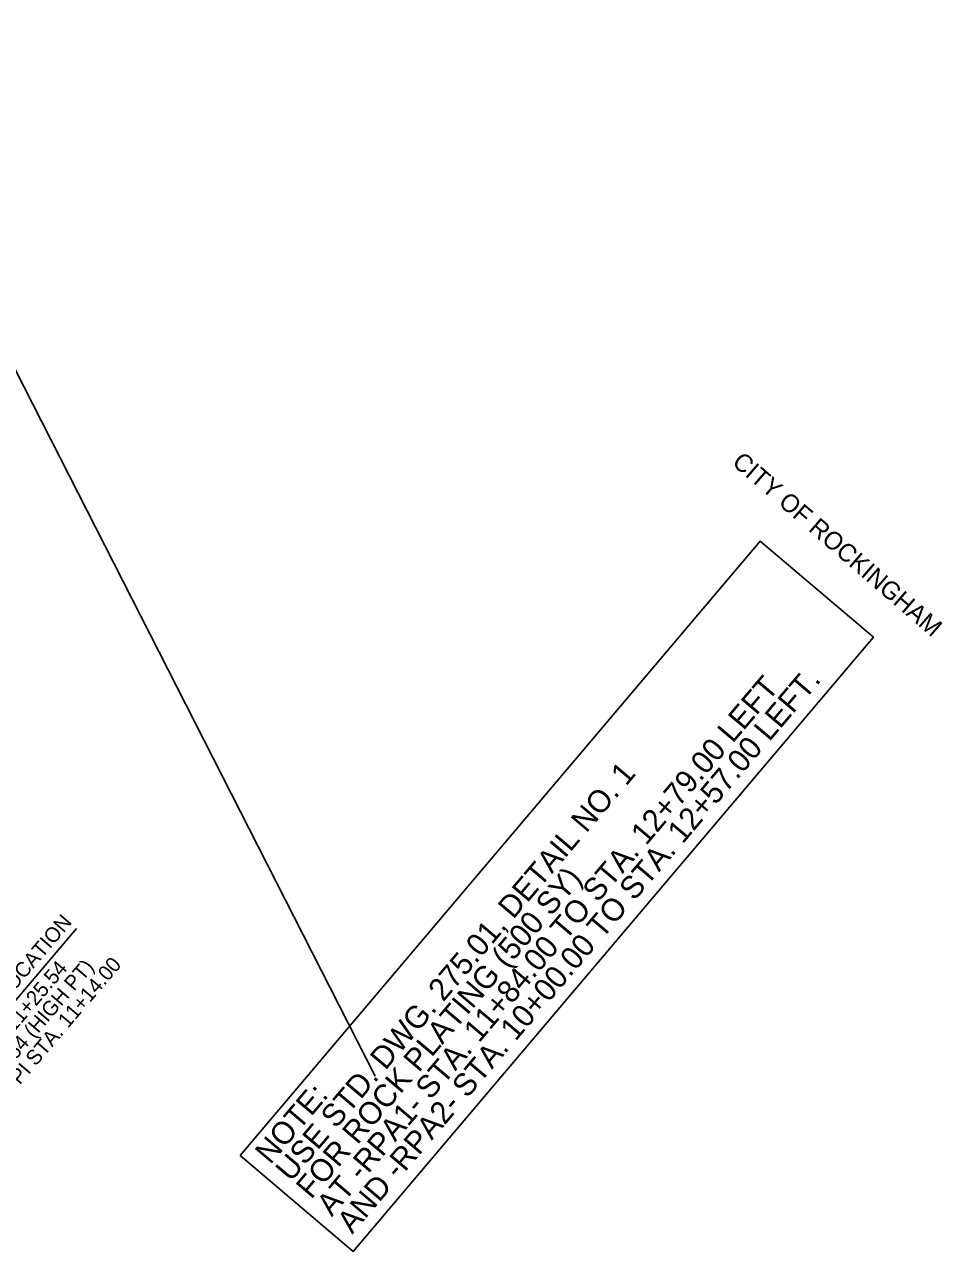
# Model space of a CAD drawing. Extents: x 1761082 to 1764358, y 421907 to 425434.
# Drawn here: x 1763174.6 to 1763482.4, y 423614.8 to 424026 of the extents above; entities that cross this region are included whole.
import ezdxf

# ---------------------------------------------------------------- set-up
doc = ezdxf.new("R2010")
doc.units = 0
for name, color, linetype in [('Prop Mkg Solid White Multiple Diagonals V8i', 7, 'Continuous'), ('Prop Mkg Solid Yel Skip LT', 7, 'Continuous'), ('Prop Mkg Solid Yel Skip RT', 7, 'Continuous'), ('Scratch_Level_1', 7, 'Continuous')]:
    doc.layers.add(name, color=color, linetype=linetype)

msp = doc.modelspace()

# ---------------------------------------------------------------- linework, layer by layer
at = {"layer": 'Prop Mkg Solid White Multiple Diagonals V8i'}
msp.add_line((1763102.71, 424045.18), (1763292.23, 423673.61), dxfattribs=at)
at = {"layer": 'Prop Mkg Solid Yel Skip RT'}
msp.add_lwpolyline([(1763246.87, 423647.02), (1763421.24, 423852.85), (1763459.23, 423820.67), (1763284.86, 423614.84)], close=True, dxfattribs=at)
at = {"layer": 'Scratch_Level_1'}
msp.add_lwpolyline([(1763192.02, 423723.1), (1763138.79, 423660.27), (1763055.17, 423635.46)], dxfattribs=at)

# ---------------------------------------------------------------- texts
at = {"layer": 'Prop Mkg Solid Yel Skip LT'}
for s, height, rotation, p in [('CITY OF ROCKINGHAM', 6, 319.1702, (1763411.5, 423878.75)), ('AT -RPA1- STA. 11+84.00 TO STA. 12+79.00 LEFT', 7.5, 49.7301, (1763277.63, 423626.25)), ('AND -RPA2- STA. 10+00.00 TO STA. 12+57.00 LEFT.', 7.5, 49.7301, (1763284.5, 423620.43)), ('USE STD. DWG. 275.01, DETAIL NO. 1', 7.5, 49.7301, (1763263.9, 423637.89)), ('FOR ROCK PLATING (500 SY)', 7.5, 49.7301, (1763270.76, 423632.07)), ('NOTE:', 7.5, 49.7301, (1763257.03, 423643.7))]:
    msp.add_text(s, height=height, rotation=rotation, dxfattribs=at).set_placement(p)
at = {"layer": 'Scratch_Level_1'}
for s, p in [('PROP. CREST LOCATION', (1763138.04, 423663.14)), ('-RPA2- VPI STA. 11+14.00', (1763154.73, 423648.99)), ('-RPA2- STA. 11+25.54', (1763144.83, 423657.39)), ('ELEV. 227.54 (HIGH PT)', (1763149.77, 423653.2))]:
    msp.add_text(s, height=5, rotation=49.5644, dxfattribs=at).set_placement(p)

doc.saveas('drawing.dxf')
